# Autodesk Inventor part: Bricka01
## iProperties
Shininess: 64.0
Length Units: 11269
Angle Units: 11279
Time Units: 11290
Mass Units: 11283
Length Display Precision: 3
Angle Display Precision: 2
Created: 2001-12
Part Number: Bricka01
Material: Steel, Mild
Document SubType Name: Modeling
Designer: Tobben
Density: 1 g/cm^3
Density: 0.0
Volumn: 0.0
Area: 0.0
PropertySet Name: Model Information
Control State: 0
Master: False
Checked Out: False
Author: Tobben
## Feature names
1. Extrusion1
2. Hole1
3. Fillet1
4. Extrusion2
